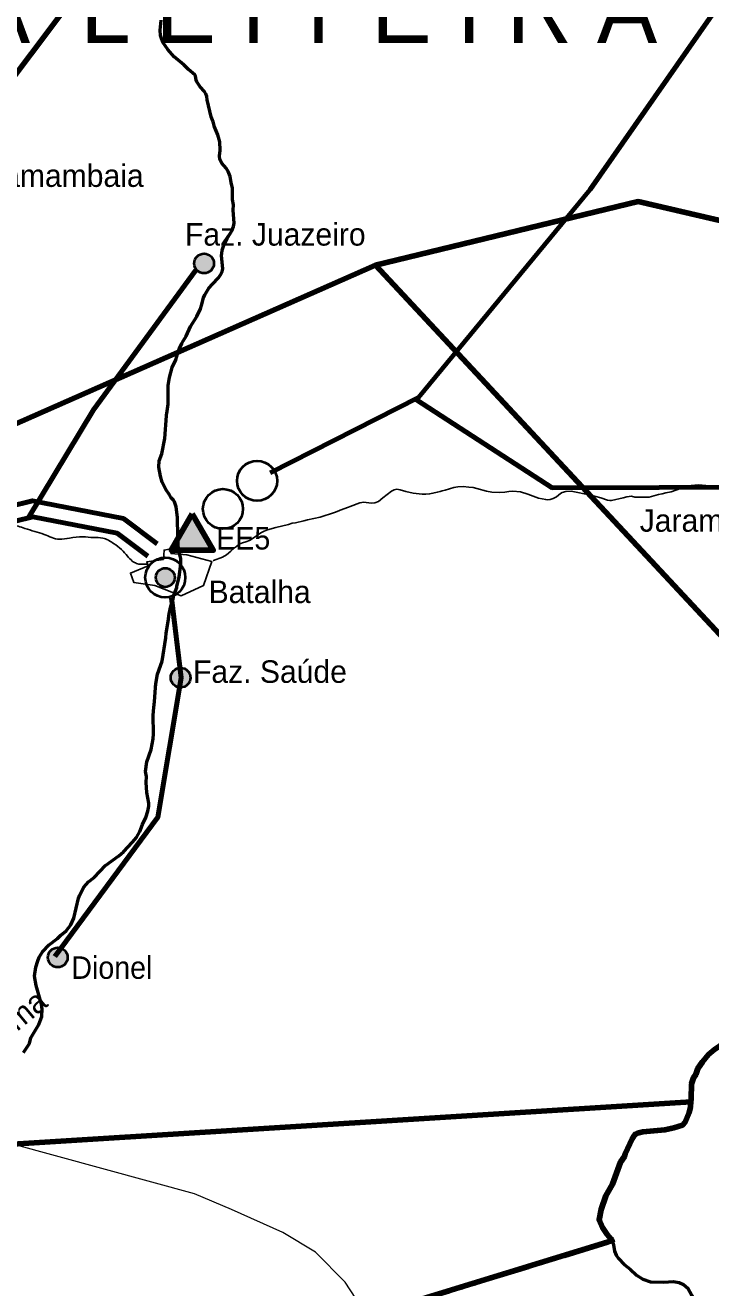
# Model space of a CAD drawing. Extents: x 553962 to 842807, y 8883888 to 9032388.
# Drawn here: x 702536 to 717768, y 8913971 to 8942036 of the extents above; entities that cross this region are included whole.
import ezdxf
from ezdxf.enums import TextEntityAlignment as Align

# ---------------------------------------------------------------- set-up
doc = ezdxf.new("R2010")
doc.units = 0
doc.header["$LTSCALE"] = 200
doc.linetypes.add('DASH_DOUBLE_DOT', pattern=[9.2, 5, -1.2, 0.3, -1.2, 0.3, -1.2])
for name, color, linetype, lineweight in [('11', 7, 'DASH_DOUBLE_DOT', 106), ('12', 7, 'Continuous', 25), ('21', 7, 'Continuous', 25), ('24', 7, 'Continuous', 25), ('28', 7, 'Continuous', 40), ('41', 7, 'Continuous', 40), ('57', 7, 'Continuous', 13), ('9', 7, 'Continuous', 90)]:
    doc.layers.add(name, color=color, linetype=linetype, lineweight=lineweight)
doc.layers.add('13', color=7, linetype='Continuous')
doc.layers.add('49', color=7, linetype='Continuous')

msp = doc.modelspace()

# ---------------------------------------------------------------- hatches: boundary and pattern name
at = {"layer": '28'}
for points in [[(706246.6, 8931173.7), (706712.7, 8930366.3), (705780.5, 8930366.3)], [(705858.5, 8929758.4, 1), (705437.7, 8929758.4, 1)]]:
    msp.add_hatch(color=256, dxfattribs=at).paths.add_polyline_path(points)
at = {"layer": '41'}
for points in [[(706728.4, 8936740.3, 1), (706290.8, 8936740.3, 1)], [(706207, 8927532.9, 1), (705769.4, 8927532.9, 1)], [(703477.6, 8921312.7, 1), (703040, 8921312.7, 1)]]:
    msp.add_hatch(color=256, dxfattribs=at).paths.add_polyline_path(points)

# ---------------------------------------------------------------- linework, layer by layer
at = {"layer": '11'}
msp.add_line((709242.2, 8913071.2), (715561.4, 8915010.8), dxfattribs=at)
for points in [[(718888.7, 8919829.8), (718698.9, 8919728.1), (718508.1, 8919414.8), (718441.7, 8919396.1), (718342.3, 8919352.7), (717962.6, 8919341.8), (717850.2, 8919266.6), (717715.4, 8919155.6), (717584.3, 8918993), (717484.9, 8918843.2), (717433.5, 8918714), (717386.5, 8918633.6), (717343.6, 8918502.1), (717334.1, 8918168.6), (717327.9, 8918103.7)], [(717327.9, 8918103.7), (717316.4, 8917983.3), (717287.5, 8917863.5), (717202.1, 8917652.5), (717139.9, 8917584.2), (716949.9, 8917526.3), (716744.6, 8917482.9), (716262.7, 8917433.2), (716138.9, 8917405.7), (716105.4, 8917390.9), (716076.8, 8917365.2), (716021.3, 8917281.8), (715870.4, 8916945.9), (715855.1, 8916891.8), (715765.5, 8916761), (715585.2, 8916273.3), (715439.9, 8916014.5), (715332.6, 8915712.1), (715285.6, 8915483), (715360.4, 8915309.1), (715466.5, 8915151.7), (715544.8, 8915057.8), (715568.8, 8915033.9), (715582.8, 8914999.5), (715585.3, 8914991.8)]]:
    msp.add_lwpolyline(points, dxfattribs=at)
at = {"layer": '12'}
for points in [[(709408.8, 8931206.7), (709506, 8931244.1), (709530.5, 8931254.4), (709718.5, 8931325.6), (709756.5, 8931340.2), (709970.9, 8931418.8), (710057.5, 8931433), (710222.4, 8931413.2), (710303.9, 8931419.1), (710382.8, 8931452.2), (710482.4, 8931530.5), (710672.9, 8931677.7), (710731.3, 8931706.9)], [(710731.3, 8931706.9), (710792.4, 8931720.3), (710870, 8931709.1), (710995.6, 8931673.3), (711155.5, 8931637), (711358.4, 8931611), (711439, 8931609.2), (711519.6, 8931616.5), (711595.6, 8931631.9), (711691.4, 8931654.4), (711758.3, 8931674.8), (711801.8, 8931686.3), (711865.2, 8931703.9)], [(711865.2, 8931703.9), (712062.8, 8931758.7), (712149.2, 8931774.2), (712270.1, 8931781.1), (712394.1, 8931770.4), (712486.3, 8931756.9), (712570, 8931737.7), (712782.6, 8931677.3), (712904.8, 8931658.7), (713073.1, 8931649.7), (713192.9, 8931656.7), (713282.3, 8931671.3), (713370.2, 8931678.6), (713537.4, 8931664.2), (713701.3, 8931615.9), (713941.9, 8931526.7), (714100.3, 8931490.7), (714142.1, 8931488.3), (714201.7, 8931495.9), (714265.5, 8931516.4), (714337.6, 8931556.1), (714431.9, 8931628.3), (714468.7, 8931648.4), (714547.9, 8931667.9), (714667.4, 8931678.5), (715103.5, 8931588.9), (715323.4, 8931530.2), (715472.8, 8931481.2), (715522.4, 8931471.9), (715561.6, 8931473.7), (715819.4, 8931527.1), (715907.5, 8931556.1), (716007, 8931568.4), (716078.4, 8931547.1), (716324.2, 8931543.6)], [(716324.2, 8931543.6), (716403.5, 8931548.6), (716611, 8931605.6), (716690.2, 8931616.7), (716773.7, 8931642.7), (716891.8, 8931664.4), (717093.4, 8931739.1), (717215.6, 8931777.9), (717335.2, 8931806.9), (717497.8, 8931823.2), (717656.3, 8931805.2), (717701.6, 8931794.1), (717788.3, 8931763.5), (718097.5, 8931715.5), (718256.9, 8931697.3), (718293.2, 8931696)], [(708723.4, 8931020.2), (708811.5, 8931041), (709092.4, 8931097.6), (709408.8, 8931206.7)], [(707006.6, 8930266.8), (707103.7, 8930343), (707184.8, 8930419.8), (707230.2, 8930449.4), (707290.2, 8930499.3), (707360.5, 8930533.4), (707440.2, 8930552.8), (707519.1, 8930582), (707648.7, 8930663), (707774.6, 8930753.3), (707847.3, 8930792.2), (707921.9, 8930818.9), (708100.7, 8930870.7), (708389.3, 8930937.4), (708468.4, 8930964.3), (708541.7, 8930977.4), (708723.4, 8931020.2)], [(706708.4, 8930134.1), (706715.6, 8930134.1), (706921.2, 8930211.8), (707006.6, 8930266.8)]]:
    msp.add_lwpolyline(points, dxfattribs=at)
msp.add_spline([(697097.5, 8934365.4), (697137.8, 8934298.3), (697070.7, 8934204.4), (696976.8, 8934097.1), (696963.4, 8933962.9), (696950, 8933681.2), (696923.2, 8933466.6), (696990.2, 8933278.7), (697097.5, 8933131.2), (697285.2, 8932889.7), (697486.4, 8932795.8), (697768, 8932648.2), (698036.2, 8932460.4), (698210.5, 8932205.5), (698344.6, 8932044.5), (698559.1, 8931829.8), (698787.1, 8931749.3), (698948, 8931628.6), (699390.5, 8931266.4), (699725.7, 8931105.4), (700114.6, 8930971.2), (700651, 8930850.5), (701147.1, 8930716.3), (701442.1, 8930609), (701723.7, 8930649.2), (702072.3, 8930823.6), (702233.2, 8930904.1), (702528.2, 8930850.5), (702957.3, 8930716.3), (703292.6, 8930609), (703520.5, 8930635.8), (703815.5, 8930662.7), (704056.9, 8930649.2), (704258, 8930635.8), (704499.4, 8930515.1), (704673.7, 8930380.9), (704807.8, 8930233.3), (704915.1, 8930126), (705008.9, 8930072.4), (705236.9, 8930058.9)], degree=3, dxfattribs=at)
at = {"layer": '21'}
msp.add_lwpolyline([(706124.6, 8930262.6), (705772.7, 8930291), (705798.2, 8930406.1), (705622.6, 8930367.7), (705604.9, 8930160.7), (705235.9, 8930107), (705266.5, 8930017.5), (704872.7, 8929859.6), (704949.4, 8929648.4), (705414.2, 8929583), (706002.8, 8929352.6), (706496.2, 8929580.5), (706680.1, 8930116.3)], close=True, dxfattribs=at)
at = {"layer": '24', "lineweight": 53}
for points in [[(707112.4, 8938537.6), (707087.7, 8938670.6), (707047.5, 8938783.2), (706998.9, 8938860.1), (706901.1, 8938969.2), (706857.7, 8939050), (706854.8, 8939130.1), (706866.7, 8939261.7), (706857.8, 8939446.3), (706814.8, 8939599.8), (706742.2, 8939780.9), (706712.9, 8939886.3), (706669.8, 8939997.2), (706579.6, 8940379.4), (706570.6, 8940449.9), (706551.5, 8940509.3), (706520.2, 8940562.7), (706419.5, 8940668.8), (706347.5, 8940779.5), (706331.3, 8940817.8), (706319.7, 8940908.8), (706302.5, 8940937.1), (706163, 8941049.9), (706059.8, 8941158.8), (705847.9, 8941335.2), (705702.7, 8941495.4), (705602.1, 8941646.2), (705560.8, 8941741.3), (705543.5, 8941811.5), (705536.3, 8941930.6), (705555.5, 8942152.9)], [(706694.7, 8936277.5), (706830.5, 8936420.4), (706877.2, 8936486.3), (706914.6, 8936562.2), (706925.8, 8936622), (706895.3, 8936909.3), (706911, 8937033.7), (706943.3, 8937127.2), (707023.2, 8937296.1), (707124.8, 8937469.7), (707160.2, 8937564.5), (707176.9, 8937639.3), (707157.3, 8937927.7), (707160, 8938043.5), (707144.2, 8938159.5), (707144.9, 8938416), (707112.4, 8938537.6)], [(706455.8, 8935807.1), (706498.6, 8935977.7), (706525, 8936043.1), (706615.1, 8936193.7), (706694.7, 8936277.5)], [(706053.6, 8935025.3), (706115.4, 8935124.2), (706210, 8935340.8), (706345.4, 8935560.9), (706345.4, 8935560.9), (706430.2, 8935735.6), (706455.8, 8935807.1)], [(705957, 8934832.6), (706016.1, 8934965.2), (706053.6, 8935025.3)], [(705904.4, 8934674.1), (705942.9, 8934801.1), (705957, 8934832.6)], [(705678, 8933377.8), (705684.3, 8933403.1), (705709.2, 8933609.6), (705711.7, 8934031.1), (705741.1, 8934209.4), (705803.6, 8934425.7), (705881, 8934596.9), (705904.4, 8934674.1)], [(705923, 8930675.2), (705922.4, 8931088), (705890.3, 8931333.3), (705852.8, 8931442.3), (705831.3, 8931475.9), (705777.1, 8931528.7), (705743, 8931598.9), (705663.1, 8931713.6), (705581.9, 8931877.1), (705542.5, 8932009.4), (705503.3, 8932209.2), (705508.2, 8932351.5), (705569.4, 8932508), (705640.5, 8932849.9), (705671.7, 8933352.4), (705678, 8933377.8)], [(705981.1, 8930233.2), (705937.6, 8930459), (705923, 8930675.2)], [(705906.7, 8929556.8), (705952.7, 8929774.7), (705995, 8930056.4), (705991.2, 8930180.9), (705981.1, 8930233.2)], [(705714.4, 8928785), (705737.3, 8928951.8), (705774, 8929122.5), (705823.8, 8929288.7), (705837.1, 8929367.7), (705902.7, 8929538.2), (705906.7, 8929556.8)], [(705581.6, 8927900.5), (705661.4, 8928419), (705668.1, 8928525.9), (705714.4, 8928785)], [(705429.5, 8927325.7), (705443, 8927442.9), (705477.8, 8927613.5), (705581.6, 8927900.5)], [(703328.7, 8921805.4), (703443, 8921908.1), (703548.7, 8922036.8), (703617.1, 8922184), (703718.8, 8922634.2), (703746.2, 8922702.2), (703835.8, 8922872.4), (703941.7, 8922992.8), (704066.1, 8923087.4), (704318, 8923358.7), (704612.5, 8923568.7), (704719.2, 8923658.3), (704922.8, 8923872.7), (705008.7, 8923982.7), (705085.3, 8924116.9), (705144.1, 8924270.4), (705217.1, 8924423.9), (705261.2, 8924562.9), (705283, 8924679.2), (705282.9, 8924744.8), (705239.7, 8924977.1), (705221.2, 8925199.9), (705230.3, 8925333.3), (705211.7, 8925444.3), (705241.2, 8925661.6), (705335.2, 8925935.9), (705376.3, 8926171.8), (705383.6, 8926283.7), (705379.5, 8926700.1), (705390.8, 8926871), (705410.9, 8927000.7), (705427.2, 8927305.4), (705429.5, 8927325.7)], [(702493.5, 8919198.3), (702630.7, 8919399.1), (702659.6, 8919524.5), (702838.4, 8919824.3), (702905.9, 8919998.5), (702914.2, 8920160.2), (702900, 8920271.5), (702779.5, 8920686.8), (702738.4, 8920898.1), (702772.1, 8921093.7), (702813.3, 8921239.1), (702844.7, 8921319.1), (702917.3, 8921435.8), (703064, 8921594.2), (703249.3, 8921734.1), (703328.7, 8921805.4)], [(717850.2, 8919266.6), (717715.4, 8919155.6), (717584.3, 8918993), (717484.9, 8918843.2), (717433.5, 8918714), (717386.5, 8918633.6), (717343.6, 8918502.1), (717334.1, 8918168.6), (717316.4, 8917983.3), (717287.5, 8917863.5), (717202.1, 8917652.5), (717139.9, 8917584.2), (716949.9, 8917526.3), (716744.6, 8917482.9), (716262.7, 8917433.2), (716138.9, 8917405.7), (716105.4, 8917390.9), (716076.8, 8917365.2), (716021.3, 8917281.8), (715870.4, 8916945.9), (715855.1, 8916891.8), (715765.5, 8916761), (715585.2, 8916273.3), (715439.9, 8916014.5), (715332.6, 8915712.1), (715285.6, 8915483), (715360.4, 8915309.1), (715466.5, 8915151.7), (715544.8, 8915057.8), (715568.8, 8915033.9), (715582.8, 8914999.5)], [(715582.8, 8914999.5), (715607.3, 8914926.5), (715630.8, 8914782.1), (715664.2, 8914698.4), (715720.4, 8914621.3), (715841.4, 8914484.8), (715976.3, 8914382.9), (716121.9, 8914251.7), (716262.7, 8914158.2), (716430.6, 8914102.4), (716723.3, 8914098.2), (716931, 8914106.3), (717067.3, 8914089.8), (717160, 8914040), (717258.6, 8913960.8), (717350.2, 8913798.9), (717444.9, 8913569.6), (717500.7, 8913495.3), (717620.4, 8913403.7), (717696.9, 8913374.6), (717753.4, 8913338.3), (717771.3, 8913315.3)]]:
    msp.add_lwpolyline(points, dxfattribs=at)
at = {"layer": '24'}
for points in [[(705581.6, 8927900.5), (705661.4, 8928419), (705668.1, 8928525.9), (705714.4, 8928785)], [(705429.5, 8927325.7), (705443, 8927442.9), (705477.8, 8927613.5), (705581.6, 8927900.5)], [(703328.7, 8921805.4), (703443, 8921908.1), (703548.7, 8922036.8), (703617.1, 8922184), (703718.8, 8922634.2), (703746.2, 8922702.2), (703835.8, 8922872.4), (703941.7, 8922992.8), (704066.1, 8923087.4), (704318, 8923358.7), (704612.5, 8923568.7), (704719.2, 8923658.3), (704922.8, 8923872.7), (705008.7, 8923982.7), (705085.3, 8924116.9), (705144.1, 8924270.4), (705217.1, 8924423.9), (705261.2, 8924562.9), (705283, 8924679.2), (705282.9, 8924744.8), (705239.7, 8924977.1), (705221.2, 8925199.9), (705230.3, 8925333.3), (705211.7, 8925444.3), (705241.2, 8925661.6), (705335.2, 8925935.9), (705376.3, 8926171.8), (705383.6, 8926283.7), (705379.5, 8926700.1), (705390.8, 8926871), (705410.9, 8927000.7), (705427.2, 8927305.4), (705429.5, 8927325.7)], [(702493.5, 8919198.3), (702630.7, 8919399.1), (702659.6, 8919524.5), (702838.4, 8919824.3), (702905.9, 8919998.5), (702914.2, 8920160.2), (702900, 8920271.5), (702779.5, 8920686.8), (702738.4, 8920898.1), (702772.1, 8921093.7), (702813.3, 8921239.1), (702844.7, 8921319.1), (702917.3, 8921435.8), (703064, 8921594.2), (703249.3, 8921734.1), (703328.7, 8921805.4)]]:
    msp.add_lwpolyline(points, dxfattribs=at)
at = {"layer": '28', "lineweight": 80}
for points in [[(720171.2, 8945676.6), (715086.9, 8938383.2), (711274.8, 8933762.2), (707980.3, 8932086.5)], [(702599.4, 8931081), (704056.3, 8933490.2), (706326, 8936590)], [(697058, 8934251.6), (697325.6, 8933082.8), (699807.6, 8931256.7), (701608.2, 8930842.7), (702703.2, 8931110.6), (704576.9, 8930745.3), (705258.2, 8930234)], [(697395.3, 8934328.9), (697634.3, 8933285.4), (699955, 8931577.9), (701605.8, 8931198.4), (702694.8, 8931464.8), (704721.1, 8931069.8), (705465.9, 8930510.8)], [(719003.5, 8931765.7), (714243.1, 8931755.7), (711229.2, 8933713)], [(705785.7, 8929308), (705997.8, 8927532.2), (705483, 8924431.7), (703194, 8921331.7)]]:
    msp.add_lwpolyline(points, dxfattribs=at)
at = {"layer": '28', "lineweight": 90}
msp.add_lwpolyline([(706246.6, 8931173.7), (706712.7, 8930366.3), (705780.5, 8930366.3)], close=True, dxfattribs=at)
at = {"layer": '28'}
for centre, radius in [((707687.8, 8931909), 444.4), ((706928.9, 8931283.6), 444.4), ((705648.1, 8929758.4), 444.4), ((705648.1, 8929758.4), 210.4)]:
    msp.add_circle(centre, radius, dxfattribs=at)
at = {"layer": '41'}
for centre in [(706509.6, 8936740.3), (705988.2, 8927532.9), (703258.8, 8921312.7)]:
    msp.add_circle(centre, 218.8, dxfattribs=at)
at = {"layer": '57'}
msp.add_lwpolyline([(710120.3, 8913369), (709646.4, 8914096), (708983, 8914759.8), (708256.3, 8915202.3), (707118.9, 8915708.1), (706297.5, 8916055.8), (702263.2, 8917164.2)], dxfattribs=at)
at = {"layer": '9'}
for p, q in [((710319.1, 8936704.6), (720989.4, 8925252.2)), ((702263.2, 8917164.2), (717332.2, 8918103.3)), ((710134.6, 8913345.1), (715561.4, 8915010.8))]:
    msp.add_line(p, q, dxfattribs=at)
for points in [[(705509.2, 8948874.2), (705653.5, 8945380.8), (701918.9, 8940415.3), (694874, 8947402.7)], [(696242, 8937672.8), (702061.8, 8937200.5), (702208.9, 8933124.7), (710319.1, 8936704.6), (716154, 8938115.2), (724825.2, 8936103.1), (730092.7, 8935013.9)], [(718888.7, 8919829.8), (718698.9, 8919728.1), (718508.1, 8919414.8), (718441.7, 8919396.1), (718342.3, 8919352.7), (717962.6, 8919341.8), (717850.2, 8919266.6), (717715.4, 8919155.6), (717584.3, 8918993), (717484.9, 8918843.2), (717433.5, 8918714), (717386.5, 8918633.6), (717343.6, 8918502.1), (717334.1, 8918168.6), (717327.9, 8918103.7)], [(717327.9, 8918103.7), (717316.4, 8917983.3), (717287.5, 8917863.5), (717202.1, 8917652.5), (717139.9, 8917584.2), (716949.9, 8917526.3), (716744.6, 8917482.9), (716262.7, 8917433.2), (716138.9, 8917405.7), (716105.4, 8917390.9), (716076.8, 8917365.2), (716021.3, 8917281.8), (715870.4, 8916945.9), (715855.1, 8916891.8), (715765.5, 8916761), (715585.2, 8916273.3), (715439.9, 8916014.5), (715332.6, 8915712.1), (715285.6, 8915483), (715360.4, 8915309.1), (715466.5, 8915151.7), (715544.8, 8915057.8), (715568.8, 8915033.9), (715582.8, 8914999.5), (715585.3, 8914991.8)], [(717327.9, 8918103.7), (717316.4, 8917983.3), (717287.5, 8917863.5), (717202.1, 8917652.5), (717139.9, 8917584.2), (716949.9, 8917526.3), (716744.6, 8917482.9), (716262.7, 8917433.2), (716138.9, 8917405.7), (716105.4, 8917390.9), (716076.8, 8917365.2), (716021.3, 8917281.8), (715870.4, 8916945.9), (715855.1, 8916891.8), (715765.5, 8916761), (715585.2, 8916273.3), (715439.9, 8916014.5), (715332.6, 8915712.1), (715285.6, 8915483), (715360.4, 8915309.1), (715466.5, 8915151.7), (715544.8, 8915057.8), (715568.8, 8915033.9), (715582.8, 8914999.5), (715585.3, 8914991.8)]]:
    msp.add_lwpolyline(points, dxfattribs=at)

# ---------------------------------------------------------------- texts
at = {"layer": '13'}
msp.add_text('B A C I A  L E I T E I R A', height=1500, dxfattribs=at).set_placement((705486.9, 8941643.8), align=Align.CENTER)
at = {"layer": '28', "width": 0.95}
msp.add_text('EE5', height=500, dxfattribs=at).set_placement((706780, 8930381.2))
at = {"layer": '41'}
for s, p in [('Faz. Samambaia', (700112.6, 8938443.4)), ('Faz. Juazeiro', (706086, 8937137.8)), ('Jaramataia', (716190.3, 8930776.7)), ('Batalha', (706611.1, 8929191.2)), ('Faz. Saúde', (706264, 8927418.1))]:
    msp.add_text(s, height=500, dxfattribs=at).set_placement(p)
at = {"layer": '41', "width": 0.95}
msp.add_text('Dionel', height=500, dxfattribs=at).set_placement((703560.5, 8920837.7))
at = {"layer": '49'}
msp.add_text('Rio Ipanema', height=500, rotation=39.92, dxfattribs=at).set_placement((701615.3, 8919036.7), align=Align.CENTER)

doc.saveas('drawing.dxf')
